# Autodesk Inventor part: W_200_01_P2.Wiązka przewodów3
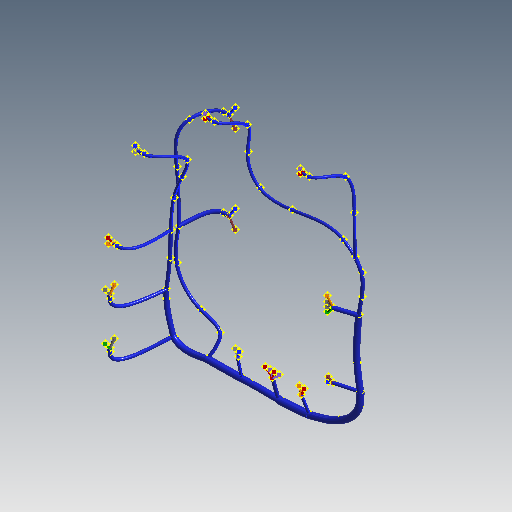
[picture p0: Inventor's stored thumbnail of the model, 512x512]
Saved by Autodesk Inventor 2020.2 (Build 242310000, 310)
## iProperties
Key:2|1|1|0|4|0|0|0|1|0|0|0|Level:2: <CableProperty entityType="Connector" version="1.0"><ID editable="" value=""/><UserDefined/><Name editable="True" value=""/><Refdes editable="True" value="PCB_1
Key:2|1|1|0|4|0|0|0|2|0|0|0|Level:2: <CableProperty entityType="Connector" version="1.0"><ID editable="" value=""/><UserDefined/><Name editable="True" value=""/><Refdes editable="True" value="S_150
Key:2|1|1|0|4|0|0|0|3|0|0|0|Level:2: <CableProperty entityType="Connector" version="1.0"><ID editable="" value=""/><UserDefined/><Name editable="True" value=""/><Refdes editable="True" value="S_150
Key:2|1|1|0|4|0|0|0|4|0|0|0|Level:2: <CableProperty entityType="Connector" version="1.0"><ID editable="" value=""/><UserDefined/><Name editable="True" value=""/><Refdes editable="True" value="SW_10
Key:2|1|1|0|4|0|0|0|5|0|0|0|Level:2: <CableProperty entityType="Connector" version="1.0"><ID editable="" value=""/><UserDefined/><Name editable="True" value=""/><Refdes editable="True" value="SW_10
Key:2|1|1|0|4|0|0|0|6|0|0|0|Level:2: <CableProperty entityType="Connector" version="1.0"><ID editable="" value=""/><UserDefined/><Name editable="True" value=""/><Refdes editable="True" value="KOND_
Key:2|1|1|0|4|0|0|0|13|0|0|0|Level:2: <CableProperty entityType="Connector" version="1.0"><ID editable="" value=""/><UserDefined/><Name editable="True" value=""/><Refdes editable="True" value="KOND_
Key:2|1|1|0|4|0|0|0|7|0|0|0|Level:2: <CableProperty entityType="Connector" version="1.0"><ID editable="" value=""/><UserDefined/><Name editable="True" value=""/><Refdes editable="True" value="LAMP_
Key:2|1|1|0|4|0|0|0|15|0|0|0|Level:2: <CableProperty entityType="Connector" version="1.0"><ID editable="" value=""/><UserDefined/><Name editable="True" value=""/><Refdes editable="True" value="METER
GlobalPropertyList: <PropertyList/>
Manager: www.cadconsulting.pl
Company: Fabian Stasiak CAD Consulting
Created: 2014-09
Part Number: W_200_01_P2.Wiązka przewodów3
Material: Ogólne
Document SubType Name: Modelowanie
Designer: F.Stasiak
Appearance: Ogólne
Catalog Web Link: www.expertbooks.pl
Author: F.Stasiak
Subject: Zbiór ćwiczeń. Autodesk Inventor 2020. Kurs Professional
## Parameters: d2 = 0, d3 = 0, d6 = 0, d7 = 0, d8 = 0, d9 = 0, d12 = 0, d13 = 0, d14 = 0, d15 = 0, d18 = 0, d19 = 0, d20 = 0, d21 = 0, d24 = 0, d25 = 0, d26 = 0, d27 = 0, d30 = 0, d31 = 0, d32 = 0, d33 = 0, d36 = 0, d37 = 0, d42 = 0, d43 = 0, d44 = 0, d45 = 0, d48 = 0, d49 = 0, d50 = 0, d51 = 0, d52 = 0, d53 = 0, d54 = 0, d55 = 0, d56 = 0, d57 = 0, d58 = 0, d59 = 0, d62 = 0, d63 = 0, d64 = 0, d65 = 0, d66 = 0, d67 = 0, d68 = 0, d69 = 0, d70 = 0, d71 = 0, d72 = 0, d73 = 0, d74 = 0, d75 = 0, d76 = 0, d77 = 0, d78 = 0, d79 = 0, d80 = 0, d81 = 0, d82 = 0, d83 = 0, d84 = 0, d85 = 0, d86 = 0, d87 = 0, d88 = 0, d89 = 0, d90 = 0, d91 = 0, d92 = 0, d93 = 0, d94 = 0, d95 = 0, d96 = 0, d97 = 0, d98 = 0, d99 = 0, d100 = 0, d101 = 0, d102 = 0, d103 = 0, d104 = 0, d105 = 0, d106 = 0, d107 = 0, d108 = 0, d109 = 0, d110 = 0, d111 = 0, d112 = 0, d113 = 0, d114 = 0, d115 = 0, d116 = 0, d117 = 0, d118 = 0, d119 = 0, d120 = 0, d121 = 0, d122 = 0, d123 = 0, d124 = 0, d125 = 0, d126 = 0, d127 = 0, d128 = 0, d129 = 0, d130 = 0, d131 = 0
